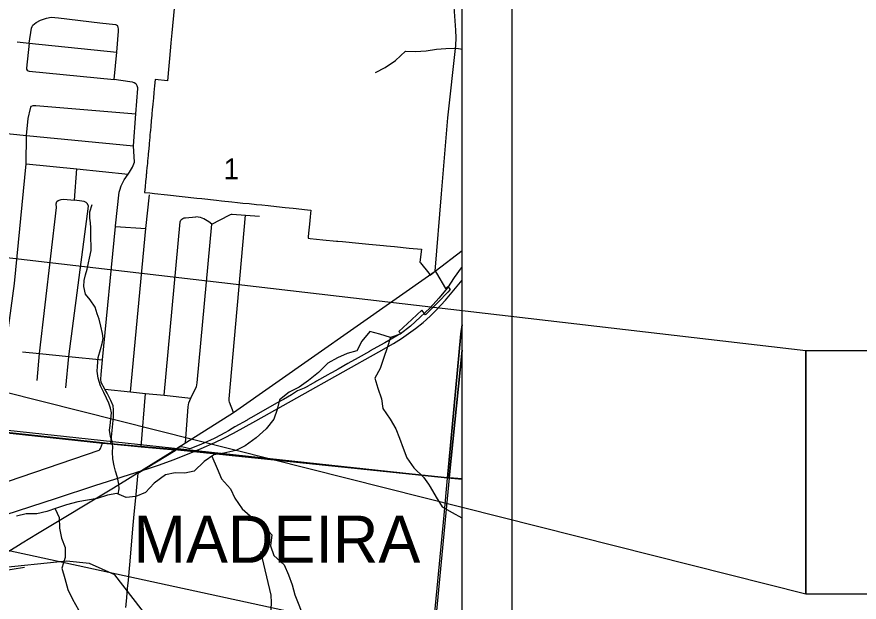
# Model space of a CAD drawing. Extents: x 0 to 34, y -3.9 to 26.2.
# Drawn here: x 8.005 to 9.699, y 16.476 to 17.653 of the extents above; entities that cross this region are included whole.
import ezdxf

# ---------------------------------------------------------------- set-up
doc = ezdxf.new("R2010")
doc.units = 0
for name, color, linetype in [('GM_X_City_Street', 7, 'Continuous'), ('GM_X_Corporation', 7, 'Continuous'), ('GM_X_Corporation_Text', 7, 'Continuous'), ('GM_X_County_Road', 7, 'Continuous'), ('GM_X_Interchange_Ramps', 7, 'Continuous'), ('GM_X_Interstate_Route', 7, 'Continuous'), ('GM_X_Minor_River', 7, 'Continuous'), ('GM_X_Rail_Line', 7, 'Continuous'), ('GM_X_Section', 7, 'Continuous'), ('GM_X_Section_Text', 7, 'Continuous'), ('GM_X_State_Shield', 7, 'Continuous'), ('SH_Data', 7, 'Continuous'), ('SH_Text', 7, 'Continuous')]:
    doc.layers.add(name, color=color, linetype=linetype)

msp = doc.modelspace()

# ---------------------------------------------------------------- linework, layer by layer
at = {"layer": 'GM_X_City_Street'}
for p, q in [((8.1202, 17.2839), (8.1253, 17.3468)), ((8.2028, 17.231), (8.264, 17.2269)), ((8.2544, 16.7882), (8.2632, 16.8954))]:
    msp.add_line(p, q, dxfattribs=at)
for points in [[(8.8459, 17.141), (8.8586, 17.2964), (8.8716, 17.4497), (8.8872, 17.5951), (8.8882, 17.6102), (8.8877, 17.6255), (8.8797, 17.7391), (8.8717, 17.9572), (8.8717, 18.0226), (8.8837, 18.2045), (8.9, 18.4043)], [(8.0292, 17.5999), (8.0343, 17.6297), (8.0354, 17.6331), (8.037, 17.6357), (8.0432, 17.6409), (8.0521, 17.6461), (8.0639, 17.6497), (8.0738, 17.6518), (8.0886, 17.6504), (8.1713, 17.6402), (8.2027, 17.637), (8.2052, 17.6362), (8.2069, 17.6354)], [(8.1938, 16.7936), (8.1989, 16.8477), (8.1991, 16.8621), (8.1981, 16.8702), (8.1938, 16.8809), (8.1861, 16.8958), (8.1818, 16.9037), (8.1743, 16.9174), (8.1733, 16.9242), (8.1742, 16.933), (8.177, 16.9626), (8.2028, 17.231), (8.2029, 17.2322), (8.2106, 17.3001), (8.2117, 17.3041), (8.2142, 17.313), (8.2205, 17.3247), (8.2282, 17.3361), (8.2312, 17.3404), (8.2372, 17.3505), (8.241, 17.3606), (8.239, 17.3932), (8.244, 17.4573), (8.2479, 17.5083), (8.2477, 17.5101), (8.2468, 17.5137), (8.2455, 17.5162), (8.2439, 17.5179), (8.2408, 17.5198), (8.2371, 17.5211), (8.2321, 17.5218), (8.2003, 17.5263), (8.2054, 17.5813), (8.2093, 17.6239), (8.2089, 17.6281), (8.2083, 17.6317), (8.2079, 17.6332), (8.2069, 17.6354)], [(8.0049, 17.6024), (8.0292, 17.5999), (8.2054, 17.5813)], [(8.0292, 17.5999), (8.0237, 17.5496), (8.0242, 17.5474), (8.0254, 17.5453), (8.0276, 17.5437), (8.0292, 17.543), (8.2003, 17.5263)], [(7.8986, 16.9786), (7.9751, 16.9718), (7.9766, 16.9721), (7.9781, 16.9726), (7.9789, 16.9733), (7.9798, 16.9739), (7.9805, 16.9755), (7.9812, 16.9775), (7.9995, 17.1166), (8.0236, 17.3573), (8.0237, 17.4142), (8.0271, 17.4483), (8.032, 17.4682), (8.0328, 17.4712), (8.0337, 17.473)], [(8.0337, 17.473), (8.0376, 17.4743), (8.0402, 17.4745), (8.0428, 17.4743), (8.244, 17.4573)], [(7.9381, 17.4226), (8.0237, 17.4142), (8.239, 17.3932)], [(8.0236, 17.3573), (8.1253, 17.3468), (8.2282, 17.3361)], [(8.0455, 16.9212), (8.0502, 16.9756), (8.0841, 17.2694), (8.0839, 17.2766), (8.0851, 17.2809), (8.0878, 17.283), (8.0935, 17.2852), (8.0987, 17.2856), (8.1202, 17.2839)], [(8.1034, 16.9065), (8.1094, 16.9695), (8.1484, 17.2717), (8.1467, 17.2766), (8.1437, 17.2795), (8.1398, 17.2813), (8.1352, 17.2821), (8.1202, 17.2839)], [(8.2332, 16.8984), (8.264, 17.2269), (8.2713, 17.2949)], [(8.3006, 16.8916), (8.333, 17.2405), (8.3342, 17.2435), (8.3362, 17.2456), (8.3384, 17.2469), (8.3411, 17.2481), (8.3438, 17.2487), (8.3647, 17.2506)], [(8.3435, 16.7956), (8.349, 16.8682), (8.3506, 16.8766), (8.3548, 16.886), (8.3605, 16.8988), (8.3656, 16.9082), (8.3673, 16.9166), (8.3964, 17.2356), (8.3908, 17.2402), (8.3806, 17.2465), (8.3738, 17.2493), (8.3647, 17.2506)], [(8.3964, 17.2356), (8.4313, 17.2536), (8.434, 17.2548), (8.4364, 17.2556), (8.4377, 17.2557), (8.4643, 17.2538), (8.4924, 17.2517)], [(8.4406, 16.8572), (8.432, 16.8774), (8.4316, 16.8804), (8.4317, 16.8842), (8.4643, 17.2538)], [(8.0158, 16.9791), (8.0502, 16.9756), (8.1094, 16.9695), (8.177, 16.9626)], [(8.1818, 16.9037), (8.2332, 16.8984), (8.2632, 16.8954), (8.3006, 16.8916), (8.3548, 16.886)], [(7.8851, 16.8268), (8.1771, 16.7951), (8.1938, 16.7936), (8.2544, 16.7882), (8.322, 16.7821)], [(7.5489, 16.7075), (7.6127, 16.7017), (7.6752, 16.6961), (7.7358, 16.6906), (7.7959, 16.6852), (7.7992, 16.6849), (7.869, 16.6786), (7.9822, 16.717), (7.984, 16.7177), (7.9878, 16.7189), (8.1703, 16.7813), (8.1711, 16.7819), (8.1716, 16.7825), (8.1726, 16.7844), (8.1771, 16.7951)], [(8.3116, 16.1821), (8.4207, 16.1738), (8.4258, 16.175), (8.428, 16.1771), (8.432, 16.1823), (8.4357, 16.1921), (8.4508, 16.3448), (8.4526, 16.3566), (8.4549, 16.3624), (8.4591, 16.3693), (8.4711, 16.3804), (8.4888, 16.3994), (8.5083, 16.4204), (8.5111, 16.4264), (8.5128, 16.4324), (8.5151, 16.4465), (8.5166, 16.4745), (8.5159, 16.4894), (8.4954, 16.5774)], [(7.9213, 16.5375), (7.9297, 16.5326), (7.9323, 16.5319), (7.9343, 16.5318), (7.9697, 16.5376), (8.0197, 16.5459)]]:
    msp.add_lwpolyline(points, dxfattribs=at)
at = {"layer": 'GM_X_Corporation'}
msp.add_lwpolyline([(8.3209, 17.6696), (8.3163, 17.6201), (8.3145, 17.6003), (8.3137, 17.5918), (8.3074, 17.5242), (8.2827, 17.5265), (8.2815, 17.5136), (8.2803, 17.5006), (8.2792, 17.4893), (8.2787, 17.4835), (8.2781, 17.4769), (8.277, 17.4657), (8.2763, 17.4574), (8.2761, 17.4551), (8.275, 17.4432), (8.2748, 17.4419), (8.2741, 17.4337), (8.2739, 17.4318), (8.2732, 17.4243), (8.2729, 17.4205), (8.2723, 17.415), (8.2718, 17.4095), (8.2714, 17.4053), (8.2707, 17.3975), (8.2706, 17.396), (8.2697, 17.387), (8.2688, 17.377), (8.2687, 17.3753), (8.2679, 17.3669), (8.2676, 17.3642), (8.2671, 17.3586), (8.2666, 17.3532), (8.2662, 17.3493), (8.2655, 17.3418), (8.2647, 17.3328), (8.2645, 17.3307), (8.2636, 17.3213), (8.2626, 17.3105), (8.2616, 17.2995), (8.2718, 17.2984), (8.2814, 17.2974), (8.3074, 17.2946), (8.3368, 17.2914), (8.3668, 17.2882), (8.3764, 17.2872), (8.4062, 17.2839), (8.4165, 17.2828), (8.4368, 17.2806), (8.4369, 17.2806), (8.4482, 17.2794), (8.4594, 17.2782), (8.4717, 17.277), (8.4863, 17.2754), (8.4976, 17.2742), (8.5099, 17.2729), (8.5269, 17.2711), (8.544, 17.2693), (8.5606, 17.2675), (8.5889, 17.2644), (8.5957, 17.2637), (8.5945, 17.2503), (8.593, 17.2354), (8.5913, 17.2175), (8.5906, 17.2104), (8.5902, 17.2074), (8.5944, 17.2069), (8.6203, 17.2044), (8.6477, 17.2016), (8.6483, 17.2016), (8.6503, 17.2014), (8.6594, 17.2005), (8.6921, 17.1974), (8.7127, 17.1954), (8.7418, 17.1926), (8.748, 17.192), (8.7641, 17.1904), (8.7937, 17.1875), (8.8182, 17.1852), (8.8152, 17.1595), (8.8165, 17.1579), (8.8329, 17.1369), (8.8358, 17.1332), (8.8462, 17.1414), (8.8486, 17.1372), (8.867, 17.1064), (8.8713, 17.1106), (8.8763, 17.104), (8.8714, 17.099), (8.8519, 17.079), (8.8376, 17.0646), (8.831, 17.0579), (8.8263, 17.0532), (8.8192, 17.0624), (8.7993, 17.0439), (8.773, 17.0196), (8.7768, 17.0156), (8.7446, 16.9971), (8.714, 16.98), (8.7139, 16.9799), (8.691, 16.9669), (8.6705, 16.9555), (8.6507, 16.9442), (8.639, 16.9376), (8.6347, 16.9352), (8.63, 16.9325), (8.6073, 16.9196), (8.6053, 16.9184), (8.5947, 16.9124), (8.5899, 16.9098), (8.5891, 16.9093), (8.5825, 16.9056), (8.5692, 16.9004), (8.5652, 16.8981), (8.5572, 16.8925), (8.5406, 16.8831), (8.5284, 16.8762), (8.5036, 16.8626), (8.4811, 16.8496), (8.4694, 16.8429), (8.4676, 16.8418), (8.4433, 16.8278), (8.4377, 16.8246), (8.43, 16.8202), (8.423, 16.8161), (8.4039, 16.8059), (8.4015, 16.8048), (8.3941, 16.8014), (8.3818, 16.7958), (8.3809, 16.7954), (8.3711, 16.7914), (8.3526, 16.7841), (8.3415, 16.7864), (8.3354, 16.7877), (8.3332, 16.7881), (8.3293, 16.7856), (8.3227, 16.7799), (8.248, 16.7345), (8.2472, 16.7286), (8.2438, 16.6922), (8.2401, 16.6523), (8.2374, 16.6227), (8.2312, 16.5502), (8.2305, 16.5436), (8.2282, 16.5191), (8.2267, 16.5035), (8.2248, 16.4841), (8.223, 16.4651)], dxfattribs=at)
at = {"layer": 'GM_X_County_Road'}
msp.add_line((8.8459, 17.141), (8.9, 17.1826), dxfattribs=at)
for points in [[(8.3364, 16.7911), (8.3435, 16.7956), (8.4406, 16.8572), (8.8459, 17.141)], [(8.8843, 16.8672), (8.898, 17.0145), (8.9, 17.0255)], [(8.8175, 16.1791), (8.8469, 16.4689), (8.8642, 16.6502), (8.871, 16.7248), (8.8843, 16.8672)], [(8.0154, 16.5947), (8.0462, 16.6134), (8.199, 16.7057), (8.322, 16.7821), (8.325, 16.7839), (8.33, 16.787), (8.3364, 16.7911)], [(7.7463, 16.4329), (7.7471, 16.4334), (7.8488, 16.4934), (7.9213, 16.5375), (8.0077, 16.59), (8.0154, 16.5947)]]:
    msp.add_lwpolyline(points, dxfattribs=at)
at = {"layer": 'GM_X_Interchange_Ramps'}
for points in [[(7.395, 14.1), (8.9, 14.1), (8.9, 20.3498)], [(8.3209, 17.6696), (8.3163, 17.6201), (8.3145, 17.6003), (8.3137, 17.5918), (8.3074, 17.5242), (8.2827, 17.5265), (8.2815, 17.5136), (8.2803, 17.5006), (8.2792, 17.4893), (8.2787, 17.4835), (8.2781, 17.4769), (8.277, 17.4657), (8.2763, 17.4574), (8.2761, 17.4551), (8.275, 17.4432), (8.2748, 17.4419), (8.2741, 17.4337), (8.2739, 17.4318), (8.2732, 17.4243), (8.2729, 17.4205), (8.2723, 17.415), (8.2718, 17.4095), (8.2714, 17.4053), (8.2707, 17.3975), (8.2706, 17.396), (8.2697, 17.387), (8.2688, 17.377), (8.2687, 17.3753), (8.2679, 17.3669), (8.2676, 17.3642), (8.2671, 17.3586), (8.2666, 17.3532), (8.2662, 17.3493), (8.2655, 17.3418), (8.2654, 17.3398), (8.2647, 17.3328), (8.2645, 17.3307), (8.2636, 17.3213), (8.2626, 17.3105), (8.2616, 17.2995), (8.2718, 17.2984), (8.2814, 17.2974), (8.3074, 17.2946), (8.3368, 17.2914), (8.3668, 17.2882), (8.3764, 17.2872), (8.4062, 17.2839), (8.4165, 17.2828), (8.4368, 17.2806), (8.4369, 17.2806), (8.4482, 17.2794), (8.4594, 17.2782), (8.4717, 17.277), (8.4863, 17.2754), (8.4976, 17.2742), (8.5099, 17.2729), (8.5269, 17.2711), (8.544, 17.2693), (8.5606, 17.2675), (8.5889, 17.2644), (8.5957, 17.2637), (8.5945, 17.2503), (8.593, 17.2354), (8.5913, 17.2175), (8.5906, 17.2104), (8.5902, 17.2074), (8.5944, 17.2069), (8.6203, 17.2044), (8.6477, 17.2016), (8.6483, 17.2016), (8.6503, 17.2014), (8.6594, 17.2005), (8.6921, 17.1974), (8.7127, 17.1954), (8.7418, 17.1926), (8.748, 17.192), (8.7641, 17.1904), (8.7937, 17.1875), (8.8182, 17.1852), (8.8152, 17.1595), (8.8165, 17.1579), (8.8329, 17.1369), (8.8358, 17.1332), (8.8462, 17.1414), (8.8486, 17.1372), (8.867, 17.1064), (8.8713, 17.1106), (8.8763, 17.104), (8.8714, 17.099), (8.8519, 17.079), (8.8376, 17.0646), (8.831, 17.0579), (8.8263, 17.0532), (8.8192, 17.0624), (8.7993, 17.0439), (8.773, 17.0196), (8.7768, 17.0156), (8.7446, 16.9971), (8.714, 16.98), (8.7139, 16.9799), (8.691, 16.9669), (8.6705, 16.9555), (8.6507, 16.9442), (8.639, 16.9376), (8.6347, 16.9352), (8.63, 16.9325), (8.6073, 16.9196), (8.6053, 16.9184), (8.5947, 16.9124), (8.5899, 16.9098), (8.5891, 16.9093), (8.5825, 16.9056), (8.5692, 16.9004), (8.5652, 16.8981), (8.5572, 16.8925), (8.5406, 16.8831), (8.5284, 16.8762), (8.5036, 16.8626), (8.4811, 16.8496), (8.4694, 16.8429), (8.4676, 16.8418), (8.4433, 16.8278), (8.4377, 16.8246), (8.43, 16.8202), (8.423, 16.8161), (8.4039, 16.8059), (8.4015, 16.8048), (8.3941, 16.8014), (8.3818, 16.7958), (8.3809, 16.7954), (8.3711, 16.7914), (8.3526, 16.7841), (8.3415, 16.7864), (8.3354, 16.7877), (8.3332, 16.7881), (8.3293, 16.7856), (8.3227, 16.7799), (8.248, 16.7345), (8.2472, 16.7286), (8.2438, 16.6922), (8.2401, 16.6523), (8.2374, 16.6227), (8.2312, 16.5502), (8.2305, 16.5436), (8.2282, 16.5191), (8.2267, 16.5035), (8.2248, 16.4841), (8.223, 16.4651)]]:
    msp.add_lwpolyline(points, dxfattribs=at)
at = {"layer": 'GM_X_Interstate_Route'}
for points in [[(7.8848, 16.8273), (8.1769, 16.7957), (8.1936, 16.7941), (8.2541, 16.7887), (8.3218, 16.7826), (8.8708, 16.7253), (8.8978, 17.015), (8.9, 17.0333), (8.9, 20.9), (3.1989, 20.9)], [(2.5468, 14.1), (8.9, 14.1), (8.9, 16.7226), (8.8708, 16.7253), (8.3218, 16.7826), (8.2541, 16.7887), (8.1936, 16.7941), (8.1769, 16.7957), (7.8848, 16.8273)]]:
    msp.add_lwpolyline(points, dxfattribs=at)
msp.add_lwpolyline([(8.9, 16.7226), (8.9, 17.0333), (8.8978, 17.015), (8.8708, 16.7253)], close=True, dxfattribs=at)
at = {"layer": 'GM_X_Minor_River'}
for points in [[(8.7262, 17.5403), (8.7452, 17.551), (8.7662, 17.5651), (8.786, 17.5837), (8.8066, 17.5826), (8.8279, 17.5841), (8.8485, 17.5875), (8.8676, 17.5886), (8.8897, 17.5894), (8.9, 17.5877)], [(8.2081, 16.693), (8.2101, 16.7035), (8.2095, 16.7131), (8.2067, 16.7261), (8.2032, 16.7387), (8.2, 16.7494), (8.1976, 16.7635), (8.1971, 16.7772), (8.1974, 16.7882), (8.1964, 16.7985), (8.1932, 16.8085), (8.1908, 16.8211), (8.1922, 16.8309), (8.1939, 16.8438), (8.1949, 16.856), (8.1932, 16.8659), (8.1897, 16.8759), (8.1849, 16.8858), (8.1794, 16.897), (8.1725, 16.9108), (8.1679, 16.9257), (8.1663, 16.9398), (8.1668, 16.9497), (8.1683, 16.9672), (8.1728, 16.9834), (8.1761, 16.9956), (8.1779, 17.0058), (8.1769, 17.0157), (8.1734, 17.0306), (8.1699, 17.0444), (8.1663, 17.0555), (8.162, 17.0689), (8.1521, 17.0835), (8.1424, 17.0947), (8.1393, 17.1104), (8.14, 17.1222), (8.1425, 17.1339), (8.1461, 17.1452), (8.1487, 17.1581), (8.1508, 17.1676), (8.1537, 17.1824), (8.1543, 17.1942), (8.1534, 17.2048), (8.1533, 17.2159), (8.1535, 17.228), (8.153, 17.2383), (8.1516, 17.2478), (8.1515, 17.2604), (8.156, 17.2751)], [(8.9, 17.1498), (8.8981, 17.1481), (8.884, 17.1287), (8.8707, 17.1074), (8.8535, 17.0869), (8.836, 17.0675), (8.8158, 17.0485), (8.796, 17.0306), (8.7758, 17.0146), (8.756, 17.0074)], [(8.756, 17.0074), (8.7346, 17.0142), (8.7148, 17.0199), (8.6984, 17.0002), (8.6881, 16.9811), (8.6687, 16.9758), (8.6493, 16.9667), (8.6302, 16.9564), (8.6111, 16.9374), (8.5913, 16.921), (8.5723, 16.9077), (8.5521, 16.8975), (8.533, 16.8826), (8.5281, 16.8628), (8.5216, 16.8434), (8.506, 16.8244), (8.4858, 16.8062), (8.4641, 16.7898), (8.445, 16.7807), (8.4206, 16.775), (8.4008, 16.7719), (8.3814, 16.7582), (8.3615, 16.7388), (8.3425, 16.735), (8.3227, 16.7358), (8.3036, 16.7316), (8.2808, 16.7149), (8.2632, 16.6959), (8.2442, 16.6879), (8.2247, 16.686), (8.2057, 16.694), (8.1866, 16.6909), (8.166, 16.6837), (8.1466, 16.6803), (8.1272, 16.6776), (8.1047, 16.6715), (8.0841, 16.6643), (8.0647, 16.6575), (8.0445, 16.6533), (8.0235, 16.6529), (8.0041, 16.6483)], [(8.756, 17.0074), (8.7491, 16.9868), (8.743, 16.9674), (8.735, 16.9454), (8.7243, 16.926), (8.7308, 16.9058), (8.7377, 16.8841), (8.7404, 16.8651), (8.7556, 16.8434), (8.7667, 16.824), (8.7743, 16.805), (8.7815, 16.7852), (8.7892, 16.7655), (8.8029, 16.7457), (8.8227, 16.7267), (8.8324, 16.7126)], [(8.3968, 16.7691), (8.4077, 16.7442), (8.4164, 16.7232), (8.434, 16.7035), (8.4427, 16.6845), (8.458, 16.6635), (8.479, 16.6445), (8.4988, 16.632), (8.5175, 16.611), (8.5144, 16.5886), (8.5217, 16.5696), (8.5422, 16.5506), (8.551, 16.5308), (8.5583, 16.5106), (8.564, 16.4901), (8.5716, 16.4699), (8.5792, 16.4505), (8.5838, 16.4266), (8.5838, 16.4045)], [(8.8324, 16.7126), (8.8361, 16.7073), (8.8479, 16.6867), (8.8601, 16.667), (8.8799, 16.6555), (8.8993, 16.6449), (8.9, 16.6444)], [(8.0815, 16.6634), (8.0895, 16.646), (8.0906, 16.624), (8.0944, 16.6042), (8.102, 16.5852), (8.1017, 16.5654), (8.0948, 16.5441), (8.1009, 16.5232), (8.1074, 16.5011), (8.1162, 16.4814), (8.1287, 16.4604)]]:
    msp.add_lwpolyline(points, dxfattribs=at)
at = {"layer": 'GM_X_Rail_Line'}
for points in [[(7.9808, 16.651), (8.084, 16.6844), (8.1614, 16.7099), (8.2716, 16.7452), (8.2912, 16.7516), (8.3192, 16.7616), (8.3513, 16.7742), (8.3752, 16.7845), (8.4029, 16.7968), (8.4208, 16.8056), (8.44, 16.8155), (8.4851, 16.8402), (8.5677, 16.8864), (8.6612, 16.9389), (8.7329, 16.9791), (8.762, 16.9959), (8.778, 17.0057), (8.7925, 17.0155), (8.8061, 17.0256), (8.8215, 17.0381), (8.8362, 17.0509), (8.8481, 17.0624), (8.867, 17.0829), (8.8836, 17.1027), (8.9, 17.1232)], [(8.9, 15.9724), (8.8703, 16.0388), (8.819, 16.1095), (8.6393, 16.2573), (8.4103, 16.3212), (8.3557, 16.3419), (8.3331, 16.3607), (8.2013, 16.5302), (8.1507, 16.5531), (8.1045, 16.5577), (7.961, 16.5433), (7.8546, 16.5443), (7.7534, 16.5507)]]:
    msp.add_lwpolyline(points, dxfattribs=at)
at = {"layer": 'GM_X_Section'}
msp.add_lwpolyline([(7.8864, 16.832), (8.8743, 16.7258), (8.7783, 15.7191), (7.7738, 15.7526)], close=True, dxfattribs=at)
at = {"layer": 'GM_X_State_Shield'}
for points in [[(8.9, 16.9823), (8.9, 17.736), (7.9734, 17.7662), (7.8864, 16.832), (8.8743, 16.7258)], [(8.9, 16.7234), (8.9, 16.9823), (8.8743, 16.7258)], [(8.9, 15.7064), (8.9, 16.7234), (8.8743, 16.7258), (8.7783, 15.7191)]]:
    msp.add_lwpolyline(points, close=True, dxfattribs=at)
at = {"layer": 'SH_Data'}
msp.add_line((9, 21), (9, 14), dxfattribs=at)
at = {"layer": 'SH_Text'}
for points in [[(9.5912, 16.9819), (9.5912, 16.4915), (5.9803, 17.4022)], [(9.5912, 16.2318), (9.5912, 15.7425), (5.8947, 17.034)], [(9.5912, 16.9819), (11.2483, 16.9819), (11.2483, 16.4915), (9.5912, 16.4915)]]:
    msp.add_lwpolyline(points, close=True, dxfattribs=at)

# ---------------------------------------------------------------- texts
at = {"layer": 'GM_X_Corporation_Text'}
msp.add_text('MADEIRA', height=0.0947, rotation=0, dxfattribs=at).set_placement((8.2392, 16.5547))
at = {"layer": 'GM_X_Section_Text'}
msp.add_text('1', height=0.0419, rotation=0, dxfattribs=at).set_placement((8.4206, 17.3259))

doc.saveas('drawing.dxf')
